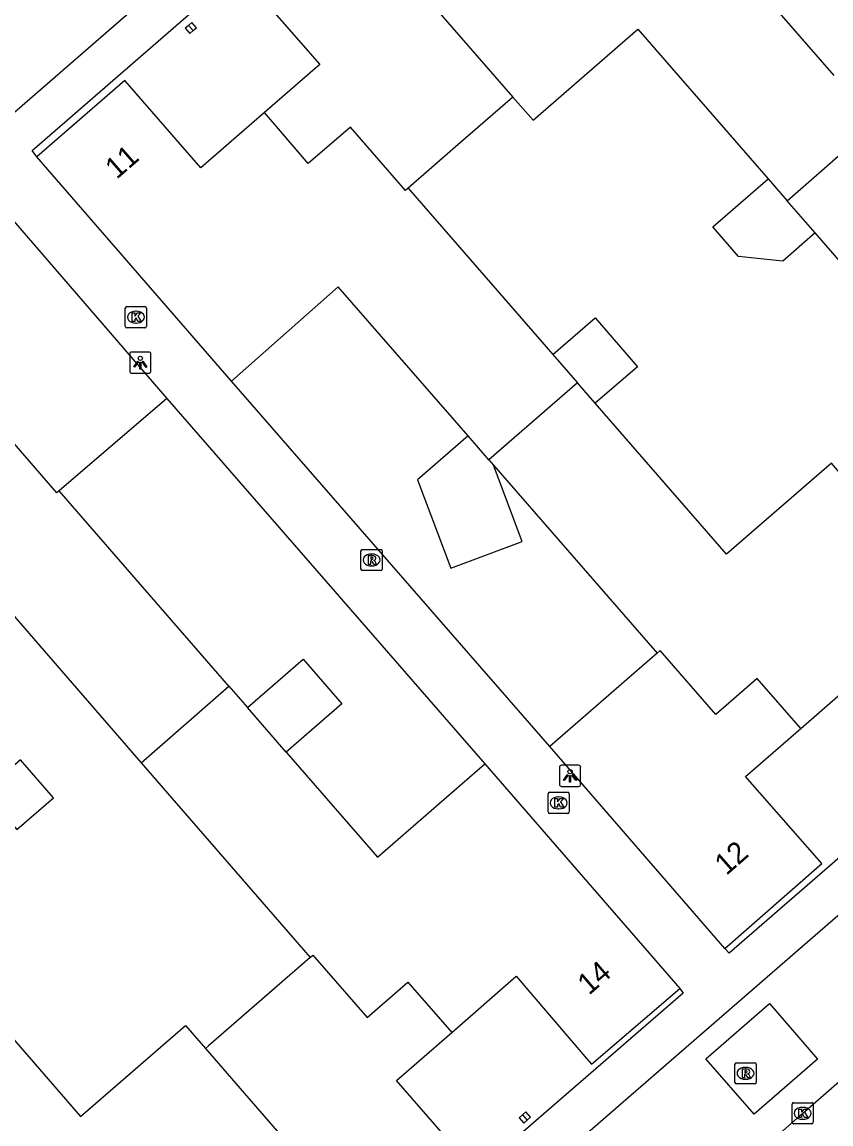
# Model space of a CAD drawing. Extents: x 155888 to 156864, y 383882 to 384671.
# Drawn here: x 156143.9 to 156182, y 384100.3 to 384152.2 of the extents above; entities that cross this region are included whole.
import ezdxf

# ---------------------------------------------------------------- set-up
doc = ezdxf.new("R2010")
doc.units = 0
for name, color, linetype in [('IMGEO_Kolk', 7, 'Continuous'), ('IMGEO_Lichtpunt', 7, 'Continuous'), ('IMGEO_Pand', 7, 'Continuous'), ('IMGEO_Pand_nummerreeks', 7, 'Continuous'), ('IMGEO_Rijbaan_lokaal_gesloten', 7, 'Continuous'), ('IMGEO_Rijbaan_lokaal_open', 7, 'Continuous'), ('IMGEO_Rioolput', 7, 'Continuous'), ('IMGEO_Voetpad_open', 7, 'Continuous')]:
    doc.layers.add(name, color=color, linetype=linetype)

msp = doc.modelspace()

# ---------------------------------------------------------------- linework, layer by layer
at = {"layer": 'IMGEO_Kolk'}
for p, q in [((156148.798, 384138.802), (156149.65, 384138.802)), ((156148.723, 384137.876), (156148.723, 384138.728)), ((156149.211, 384138.582), (156149.236, 384138.582)), ((156149.724, 384138.728), (156149.724, 384137.876)), ((156149.65, 384137.802), (156148.798, 384137.802)), ((156149.234, 384138.022), (156149.209, 384138.022)), ((156168.714, 384115.912), (156169.566, 384115.912)), ((156168.639, 384114.986), (156168.639, 384115.838)), ((156169.127, 384115.692), (156169.152, 384115.692)), ((156169.64, 384115.838), (156169.64, 384114.986)), ((156169.566, 384114.912), (156168.714, 384114.912)), ((156169.15, 384115.132), (156169.125, 384115.132)), ((156180.135, 384100.358), (156180.135, 384101.21)), ((156180.21, 384101.284), (156181.062, 384101.284)), ((156180.623, 384101.064), (156180.648, 384101.064)), ((156181.136, 384101.21), (156181.136, 384100.358)), ((156180.646, 384100.504), (156180.621, 384100.504)), ((156181.062, 384100.284), (156180.21, 384100.284))]:
    msp.add_line(p, q, dxfattribs=at)
for points in [[(156148.798, 384138.802), (156149.65, 384138.802)], [(156148.723, 384137.876), (156148.723, 384138.728)], [(156149.044, 384138.502), (156149.167, 384138.502), (156149.167, 384138.351), (156149.297, 384138.502), (156149.461, 384138.502), (156149.315, 384138.351), (156149.468, 384138.102), (156149.316, 384138.102), (156149.231, 384138.266), (156149.167, 384138.199), (156149.167, 384138.102), (156149.044, 384138.102), (156149.044, 384138.502)], [(156149.724, 384138.728), (156149.724, 384137.876)], [(156149.65, 384137.802), (156148.798, 384137.802)], [(156168.714, 384115.912), (156169.566, 384115.912)], [(156168.639, 384114.986), (156168.639, 384115.838)], [(156168.96, 384115.612), (156169.083, 384115.612), (156169.083, 384115.461), (156169.213, 384115.612), (156169.377, 384115.612), (156169.231, 384115.461), (156169.384, 384115.212), (156169.232, 384115.212), (156169.147, 384115.376), (156169.083, 384115.309), (156169.083, 384115.212), (156168.96, 384115.212), (156168.96, 384115.612)], [(156169.64, 384115.838), (156169.64, 384114.986)], [(156169.566, 384114.912), (156168.714, 384114.912)], [(156180.135, 384100.358), (156180.135, 384101.21)], [(156180.21, 384101.284), (156181.062, 384101.284)], [(156180.456, 384100.984), (156180.579, 384100.984), (156180.579, 384100.833), (156180.709, 384100.984), (156180.873, 384100.984), (156180.727, 384100.833), (156180.88, 384100.584), (156180.728, 384100.584), (156180.643, 384100.748), (156180.579, 384100.681), (156180.579, 384100.584), (156180.456, 384100.584), (156180.456, 384100.984)], [(156181.136, 384101.21), (156181.136, 384100.358)], [(156181.062, 384100.284), (156180.21, 384100.284)]]:
    msp.add_lwpolyline(points, dxfattribs=at)
for centre, start, end in [((156148.8, 384138.726), 91.552, 178.448), ((156148.8, 384138.726), 91.552, 178.448), ((156149.648, 384138.726), 1.552, 88.448), ((156149.648, 384138.726), 1.552, 88.448), ((156148.8, 384137.878), 181.552, 268.448), ((156148.8, 384137.878), 181.552, 268.448), ((156149.648, 384137.878), 271.552, 358.448), ((156149.648, 384137.878), 271.552, 358.448), ((156168.716, 384115.836), 91.552, 178.448), ((156168.716, 384115.836), 91.552, 178.448), ((156169.564, 384115.836), 1.552, 88.448), ((156169.564, 384115.836), 1.552, 88.448), ((156168.716, 384114.988), 181.552, 268.448), ((156168.716, 384114.988), 181.552, 268.448), ((156169.564, 384114.988), 271.552, 358.448), ((156169.564, 384114.988), 271.552, 358.448), ((156180.212, 384101.208), 91.552, 178.448), ((156180.212, 384101.208), 91.552, 178.448), ((156181.06, 384101.208), 1.552, 88.448), ((156181.06, 384101.208), 1.552, 88.448), ((156180.212, 384100.36), 181.552, 268.448), ((156180.212, 384100.36), 181.552, 268.448), ((156181.06, 384100.36), 271.552, 358.448), ((156181.06, 384100.36), 271.552, 358.448)]:
    msp.add_arc(centre, 0.0765, start, end, dxfattribs=at)
for centre, major_axis, ratio, start_param, end_param in [((156149.21, 384138.302), (-0.387, 0.002), 0.722429, 4.712389, 7.853982), ((156149.235, 384138.302), (-0.39, 0.002), 0.717154, 1.570796, 4.712389), ((156169.126, 384115.412), (-0.387, 0.002), 0.722429, 4.712389, 7.853982), ((156169.151, 384115.412), (-0.39, 0.002), 0.717154, 1.570796, 4.712389), ((156180.622, 384100.784), (-0.387, 0.002), 0.722429, 4.712389, 7.853982), ((156180.647, 384100.784), (-0.39, 0.002), 0.717154, 1.570796, 4.712389)]:
    msp.add_ellipse(centre, major_axis=major_axis, ratio=ratio, start_param=start_param, end_param=end_param, dxfattribs=at)
at = {"layer": 'IMGEO_Lichtpunt'}
for p, q in [((156148.932, 384136.566), (156148.932, 384135.759)), ((156148.932, 384136.566), (156148.932, 384135.759)), ((156149.834, 384136.661), (156149.026, 384136.661)), ((156149.834, 384136.661), (156149.026, 384136.661)), ((156149.928, 384135.759), (156149.928, 384136.566)), ((156149.928, 384135.759), (156149.928, 384136.566)), ((156149.026, 384135.665), (156149.834, 384135.665)), ((156149.026, 384135.665), (156149.834, 384135.665)), ((156169.179, 384117.088), (156169.179, 384116.281)), ((156169.179, 384117.088), (156169.179, 384116.281)), ((156170.081, 384117.183), (156169.273, 384117.183)), ((156170.081, 384117.183), (156169.273, 384117.183)), ((156170.175, 384116.281), (156170.175, 384117.088)), ((156170.175, 384116.281), (156170.175, 384117.088)), ((156169.273, 384116.187), (156170.081, 384116.187)), ((156169.273, 384116.187), (156170.081, 384116.187))]:
    msp.add_line(p, q, dxfattribs=at)
for points in [[(156149.306, 384136.23), (156149.345, 384136.202), (156149.157, 384135.94), (156149.119, 384135.967), (156149.306, 384136.23)], [(156149.408, 384136.182), (156149.455, 384136.182), (156149.455, 384135.86), (156149.408, 384135.86), (156149.408, 384136.182)], [(156149.518, 384136.202), (156149.556, 384136.229), (156149.743, 384135.967), (156149.704, 384135.939), (156149.518, 384136.202)], [(156169.553, 384116.752), (156169.592, 384116.724), (156169.404, 384116.462), (156169.366, 384116.489), (156169.553, 384116.752)], [(156169.655, 384116.704), (156169.702, 384116.704), (156169.702, 384116.382), (156169.655, 384116.382), (156169.655, 384116.704)], [(156169.765, 384116.724), (156169.803, 384116.751), (156169.99, 384116.489), (156169.951, 384116.461), (156169.765, 384116.724)]]:
    msp.add_lwpolyline(points, dxfattribs=at)
for centre in [(156149.431, 384136.364), (156169.678, 384116.886)]:
    msp.add_circle(centre, 0.0994, dxfattribs=at)
for centre, start, end in [((156149.026, 384136.566), 90, 180), ((156149.026, 384136.566), 90, 180), ((156149.834, 384136.566), 0, 90), ((156149.834, 384136.566), 0, 90), ((156149.026, 384135.759), 180, 270), ((156149.026, 384135.759), 180, 270), ((156149.834, 384135.759), 270, 0), ((156149.834, 384135.759), 270, 360), ((156169.273, 384117.088), 90, 180), ((156169.273, 384117.088), 90, 180), ((156170.081, 384117.088), 0, 90), ((156170.081, 384117.088), 0, 90), ((156169.273, 384116.281), 180, 270), ((156169.273, 384116.281), 180, 270), ((156170.081, 384116.281), 270, 0), ((156170.081, 384116.281), 270, 360)]:
    msp.add_arc(centre, 0.0946, start, end, dxfattribs=at)
at = {"layer": 'IMGEO_Pand'}
for points in [[(156158.722, 384158.175), (156154.301, 384154.317), (156157.884, 384150.21), (156157.663, 384150.018), (156155.274, 384147.943)], [(156158.722, 384158.175), (156166.982, 384148.678)], [(156176.089, 384156.599), (156182.1, 384149.691)], [(156151.701, 384152.056), (156151.543, 384151.918), (156151.76, 384151.669), (156151.918, 384151.807)], [(156151.918, 384151.807), (156152.076, 384151.944), (156151.859, 384152.193), (156151.701, 384152.056)], [(156151.918, 384151.807), (156151.701, 384152.056)], [(156166.982, 384148.678), (156167.933, 384147.585), (156172.875, 384151.879), (156179.01, 384144.82)], [(156155.274, 384147.943), (156152.28, 384145.342), (156148.923, 384149.208), (156148.707, 384149.457), (156144.562, 384145.858)], [(156166.982, 384148.678), (156166.847, 384148.561), (156164.279, 384146.329), (156162.048, 384144.391)], [(156162.048, 384144.391), (156161.92, 384144.28), (156159.334, 384147.253), (156157.335, 384145.539), (156155.274, 384147.943)], [(156179.901, 384143.794), (156184.071, 384147.425)], [(156153.719, 384135.289), (156144.562, 384145.858)], [(156181.222, 384142.274), (156179.698, 384140.949), (156177.611, 384141.17), (156176.406, 384142.557), (156179.01, 384144.82)], [(156179.01, 384144.82), (156179.901, 384143.794)], [(156142.457, 384143.983), (156150.675, 384134.478)], [(156162.048, 384144.391), (156168.869, 384136.542)], [(156181.222, 384142.274), (156179.901, 384143.794)], [(156187.875, 384134.618), (156181.222, 384142.274)], [(156164.869, 384132.708), (156158.754, 384139.738), (156153.719, 384135.289)], [(156168.869, 384136.542), (156170.852, 384138.266), (156172.85, 384135.968), (156170.866, 384134.244)], [(156168.869, 384136.542), (156170.025, 384135.212)], [(156170.025, 384135.212), (156165.851, 384131.579)], [(156170.866, 384134.244), (156170.025, 384135.212)], [(156150.675, 384134.478), (156145.599, 384130.118)], [(156182.941, 384130.331), (156181.99, 384131.424), (156177.048, 384127.13), (156170.866, 384134.244)], [(156145.599, 384130.118), (156145.497, 384130.03), (156142.978, 384132.929), (156141.017, 384131.23), (156138.902, 384133.671)], [(156164.869, 384132.708), (156162.487, 384130.637), (156164.065, 384126.467), (156167.426, 384127.738), (156166.067, 384131.33)], [(156165.851, 384131.579), (156164.869, 384132.708)], [(156165.851, 384131.579), (156166.067, 384131.33)], [(156166.067, 384131.33), (156173.774, 384122.471)], [(156153.605, 384120.907), (156145.599, 384130.118)], [(156137.514, 384121.094), (156142.456, 384125.383), (156149.474, 384117.296)], [(156154.479, 384119.902), (156157.102, 384122.183), (156158.927, 384120.084), (156156.303, 384117.803)], [(156173.774, 384122.471), (156168.72, 384118.074)], [(156180.549, 384118.923), (156178.496, 384121.279), (156176.544, 384119.578), (156173.919, 384122.597), (156173.774, 384122.471)], [(156180.549, 384118.923), (156183.521, 384121.515), (156186.882, 384117.658), (156187.101, 384117.406), (156190.952, 384120.761), (156191.13, 384120.916)], [(156149.474, 384117.296), (156153.605, 384120.907)], [(156153.605, 384120.907), (156154.479, 384119.902)], [(156156.303, 384117.803), (156154.479, 384119.902)], [(156176.966, 384108.553), (156181.535, 384112.552), (156177.946, 384116.653), (156178.179, 384116.857), (156180.549, 384118.923)], [(156176.966, 384108.553), (156168.72, 384118.074)], [(156156.303, 384117.803), (156160.603, 384112.856), (156165.658, 384117.25)], [(156142.058, 384115.937), (156143.607, 384114.151), (156145.339, 384115.655), (156143.79, 384117.44), (156142.058, 384115.937)], [(156149.474, 384117.296), (156157.437, 384108.121)], [(156165.658, 384117.25), (156174.844, 384106.671)], [(156139.597, 384108.722), (156146.616, 384100.634), (156151.56, 384104.925), (156152.503, 384103.838)], [(156157.437, 384108.121), (156154.56, 384105.623), (156152.639, 384103.956), (156152.503, 384103.838)], [(156157.437, 384108.121), (156157.565, 384108.232), (156160.115, 384105.291), (156162.034, 384106.965), (156164.101, 384104.595)], [(156164.101, 384104.595), (156167.134, 384107.242), (156170.463, 384103.357), (156170.68, 384103.103), (156174.844, 384106.671)], [(156160.688, 384094.403), (156165.078, 384098.215), (156161.505, 384102.33), (156161.73, 384102.527), (156164.101, 384104.595)], [(156152.503, 384103.838), (156160.688, 384094.403)], [(156167.656, 384100.461), (156167.814, 384100.599), (156167.594, 384100.85), (156167.433, 384100.709)], [(156167.433, 384100.709), (156167.274, 384100.57), (156167.494, 384100.319), (156167.656, 384100.461)], [(156167.433, 384100.709), (156167.656, 384100.461)]]:
    msp.add_lwpolyline(points, dxfattribs=at)
at = {"layer": 'IMGEO_Rijbaan_lokaal_gesloten'}
for points in [[(156096.403, 384107.059), (156182.818, 384182.155)], [(156220.134, 384142.954), (156131.822, 384066.268)], [(156179.022, 384099.365), (156180.638, 384100.784), (156183.098, 384102.929)]]:
    msp.add_lwpolyline(points, dxfattribs=at)
at = {"layer": 'IMGEO_Rijbaan_lokaal_open'}
msp.add_lwpolyline([(156181.341, 384103.336), (156178.345, 384100.742), (156176.08, 384103.358), (156179.075, 384105.952), (156181.341, 384103.336)], dxfattribs=at)
at = {"layer": 'IMGEO_Rioolput'}
for p, q in [((156159.9, 384127.36), (156160.752, 384127.36)), ((156159.825, 384126.434), (156159.825, 384127.286)), ((156160.313, 384127.14), (156160.338, 384127.14)), ((156160.826, 384127.286), (156160.826, 384126.434)), ((156160.752, 384126.36), (156159.9, 384126.36)), ((156160.336, 384126.58), (156160.311, 384126.58)), ((156177.443, 384102.242), (156177.443, 384103.094)), ((156177.518, 384103.168), (156178.37, 384103.168)), ((156177.931, 384102.948), (156177.956, 384102.948)), ((156178.444, 384103.094), (156178.444, 384102.242)), ((156178.37, 384102.168), (156177.518, 384102.168)), ((156177.954, 384102.388), (156177.929, 384102.388))]:
    msp.add_line(p, q, dxfattribs=at)
for points in [[(156159.9, 384127.36), (156160.752, 384127.36)], [(156159.825, 384126.434), (156159.825, 384127.286)], [(156160.414, 384127.058), (156160.162, 384127.06), (156160.162, 384126.66)], [(156160.162, 384126.66), (156160.286, 384126.66), (156160.286, 384126.822), (156160.297, 384126.822)], [(156160.34, 384126.979), (156160.286, 384126.979), (156160.286, 384126.898)], [(156160.286, 384126.898), (156160.338, 384126.898)], [(156160.826, 384127.286), (156160.826, 384126.434)], [(156160.752, 384126.36), (156159.9, 384126.36)], [(156160.344, 384126.793), (156160.415, 384126.66), (156160.555, 384126.66), (156160.49, 384126.786)], [(156177.443, 384102.242), (156177.443, 384103.094)], [(156177.518, 384103.168), (156178.37, 384103.168)], [(156178.444, 384103.094), (156178.444, 384102.242)], [(156178.032, 384102.866), (156177.78, 384102.868), (156177.78, 384102.468)], [(156177.78, 384102.468), (156177.904, 384102.468), (156177.904, 384102.63), (156177.915, 384102.63)], [(156177.958, 384102.787), (156177.904, 384102.787), (156177.904, 384102.706)], [(156177.904, 384102.706), (156177.956, 384102.706)], [(156177.962, 384102.601), (156178.033, 384102.468), (156178.173, 384102.468), (156178.108, 384102.594)], [(156178.37, 384102.168), (156177.518, 384102.168)]]:
    msp.add_lwpolyline(points, dxfattribs=at)
for centre, radius, start, end in [((156159.902, 384127.284), 0.0765, 91.552, 178.448), ((156159.902, 384127.284), 0.0765, 91.552, 178.448), ((156160.75, 384127.284), 0.0765, 1.552, 88.448), ((156160.75, 384127.284), 0.0765, 1.552, 88.448), ((156160.296, 384126.769), 0.0533, 26.0293, 88.6989), ((156160.322, 384127.087), 0.19, 274.7715, 282.9687), ((156160.346, 384126.883), 0.0964, 77.0061, 93.1865), ((156160.36, 384126.94), 0.0378, 276.6634, 79.6772), ((156160.413, 384126.948), 0.109, 350.3612, 89.416), ((156160.411, 384126.948), 0.112, 277.5842, 350.9817), ((156160.395, 384126.733), 0.108, 29.5134, 73.7905), ((156159.902, 384126.436), 0.0765, 181.552, 268.448), ((156159.902, 384126.436), 0.0765, 181.552, 268.448), ((156160.75, 384126.436), 0.0765, 271.552, 358.448), ((156160.75, 384126.436), 0.0765, 271.552, 358.448), ((156177.52, 384103.092), 0.0765, 91.552, 178.448), ((156177.52, 384103.092), 0.0765, 91.552, 178.448), ((156178.368, 384103.092), 0.0765, 1.552, 88.448), ((156178.368, 384103.092), 0.0765, 1.552, 88.448), ((156177.914, 384102.577), 0.0533, 26.0293, 88.6989), ((156177.94, 384102.895), 0.19, 274.7715, 282.9687), ((156177.964, 384102.691), 0.0964, 77.0061, 93.1865), ((156177.978, 384102.748), 0.0378, 276.6634, 79.6772), ((156178.031, 384102.756), 0.109, 350.3612, 89.416), ((156178.029, 384102.756), 0.112, 277.5842, 350.9817), ((156178.013, 384102.541), 0.108, 29.5134, 73.7905), ((156177.52, 384102.244), 0.0765, 181.552, 268.448), ((156177.52, 384102.244), 0.0765, 181.552, 268.448), ((156178.368, 384102.244), 0.0765, 271.552, 358.448), ((156178.368, 384102.244), 0.0765, 271.552, 358.448)]:
    msp.add_arc(centre, radius, start, end, dxfattribs=at)
for centre, major_axis, ratio, start_param, end_param in [((156160.312, 384126.86), (-0.387, 0.002), 0.722429, 4.712389, 7.853982), ((156160.337, 384126.86), (-0.39, 0.002), 0.717154, 1.570796, 4.712389), ((156177.93, 384102.668), (-0.387, 0.002), 0.722429, 4.712389, 7.853982), ((156177.955, 384102.668), (-0.39, 0.002), 0.717154, 1.570796, 4.712389)]:
    msp.add_ellipse(centre, major_axis=major_axis, ratio=ratio, start_param=start_param, end_param=end_param, dxfattribs=at)
at = {"layer": 'IMGEO_Voetpad_open'}
for points in [[(156144.562, 384145.858), (156144.327, 384146.151), (156186.698, 384182.944)], [(156219.567, 384145.116), (156177.171, 384108.334), (156176.966, 384108.553)], [(156168.72, 384118.074), (156153.719, 384135.289)], [(156150.675, 384134.478), (156165.658, 384117.25)], [(156174.844, 384106.671), (156175.007, 384106.446), (156165.495, 384098.191), (156160.684, 384093.999), (156151.467, 384085.989), (156146.66, 384081.804), (156137.468, 384073.824), (156132.659, 384069.648), (156132.453, 384069.884)]]:
    msp.add_lwpolyline(points, dxfattribs=at)

# ---------------------------------------------------------------- texts
at = {"layer": 'IMGEO_Pand_nummerreeks'}
for s, rotation, p in [('11', 40.9665, (156148.317, 384144.774)), ('12', 41.1939, (156177.036, 384111.963)), ('14', 40.5941, (156170.565, 384106.322))]:
    msp.add_text(s, height=1, rotation=rotation, dxfattribs=at).set_placement(p)

doc.saveas('drawing.dxf')
